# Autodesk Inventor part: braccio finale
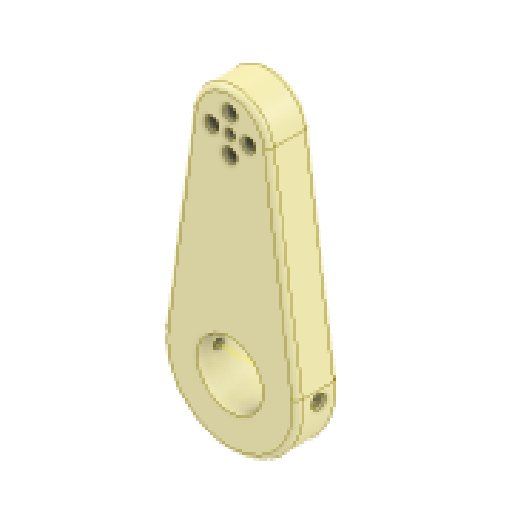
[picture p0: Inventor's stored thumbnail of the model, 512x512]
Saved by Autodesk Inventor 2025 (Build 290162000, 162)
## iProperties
Created: 2025-05
Part Number: braccio finale
Material: Nylon 6/6
Document SubType Name: Modeling
Designer: Ryzen5700u
Density: 1.13 g/cm^3
Appearance: Nylon 6
Author: Ryzen5700u
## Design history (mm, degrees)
sketch "Schizzo1"
  geometry: L1 (-25.751, 3.591)-(-14.807, 82.072); L2 (25.755, 3.559)-(14.908, 82.053); C1 r 12.55 at (0, 0); C2 r 2 at (0.049, 80); A1 r 26 centre (0, 0) between (25.755, 3.559) and (-25.751, 3.591); A2 r 15 centre (0.049, 80) between (-14.807, 82.072) and (14.908, 82.053); 2 further points
  constraints: 4 centre point, 4 coincident, 4 end point, 4 point on circle, 4 tangent
  dimensions: "d0" = 52 diameter of A1; "d2" = 25.1 diameter of C1; "d28" = 4 diameter of C2; "d29" = 30 diameter of A2; "d30" = 80 distance of point (0.049, 80) point (0, 0)
extrude "Estrusione1" new body sketch "Schizzo1" distance "d3" = 16; taper "d4" = 0 deg
fillet "Raccordo1" dims "d5" = 1
sketch "Schizzo5"
  geometry: C1 r 2 at (-0.049, 80) reference; 2 further points
  constraints: 1 coincident
hole "Foro4" sketch "Schizzo5" at (-0.049, 80) diameter "d31" = 3.4; stored, may be unused: countersink angle "d35" = 90 deg, drill point angle "d37" = 118 deg; dims "d32" = 6, "d33" = 7, "d34" = 5, "d36" = 8
sketch "Schizzo6"
  geometry: L1 (-12.55, 16)-(12.55, 16) reference; C1 r 1.6 at (0, 8); 2 further points
  constraints: 1 centre point, 1 coincident
  dimensions: "d38" = 8 distance from line of L1 point (0, 8); "d39" = 3.2 diameter of C1
extrude "Estrusione2" cut sketch "Schizzo6" extent not by distance; stored distance "d40" = 0; taper "d41" = 0 deg
node "Asse di lavoro1"
node "Piano di lavoro1"
sketch "Schizzo7"
  geometry: 4 further points
  constraints: 1 vertical alignment
hole "Foro5" sketch "Schizzo7" at (0, 8) diameter "d43" = 3.4; stored, may be unused: countersink angle "d47" = 90 deg, drill point angle "d49" = 118 deg; dims "d44" = 6, "d45" = 6, "d46" = 2, "d48" = 8
mirror "Speculare1"
fillet "Raccordo2" dims "d50" = 1
sketch "Schizzo9"
  geometry: L1 (13.917, 81.916)-(24.765, 3.422) reference; L2 (-24.76, 3.453)-(-13.817, 81.934) reference; C1 r 2 at (0.049, 80) reference; C2 r 12.55 at (0, 0) reference; C3 r 1.6 at (0.049, 73) reference; C4 r 1.6 at (0.049, 87) reference; C5 r 1.6 at (7.049, 80) reference; C6 r 1.6 at (-6.951, 80) reference; A1 r 25 centre (0, 0) between (-24.76, 3.453) and (24.765, 3.422) reference; A2 r 14 centre (0.049, 80) between (13.917, 81.916) and (-13.817, 81.934) reference; 1 further point
hole "Foro6" sketch "Schizzo9" at (-6.951, 80), (0.049, 73), (7.049, 80), (0.049, 87) diameter "d51" = 3.2; stored, may be unused: countersink angle "d55" = 90 deg, drill point angle "d57" = 118 deg; dims "d52" = 6, "d53" = 5.5, "d54" = 4, "d56" = 8
sketch "Schizzo11"
  geometry: C1 r 13.5 at (0, 0); C2 r 12.55 at (0, 0) reference; A1 r 26 centre (0, 0) between (-25.755, 3.559) and (25.751, 3.591) reference; 1 further point
  constraints: 1 centre point, 1 coincident
  dimensions: "d58" = 27 diameter of C1
extrude "Estrusione3" join sketch "Schizzo11" distance "d59" = 4; taper "d60" = 0 deg
node "Piano di lavoro2"
sketch "Schizzo12"
  geometry: C1 r 1.7 at (0, 8) reference; 2 further points
  constraints: 1 coincident
hole "Foro7" sketch "Schizzo12" at (0, 8) diameter "d62" = 3.4; stored, may be unused: countersink angle "d66" = 90 deg, drill point angle "d68" = 118 deg; dims "d63" = 6, "d64" = 5.5, "d65" = 4, "d67" = 8
node "Piano di lavoro3"
sketch "Schizzo13"
  geometry: L1 (-3.233, 8)-(-1.617, 10.8); L2 (-1.617, 10.8)-(1.617, 10.8); L3 (1.617, 10.8)-(3.233, 8); L4 (3.233, 8)-(1.617, 5.2); L5 (1.617, 5.2)-(-1.617, 5.2); L6 (-1.617, 5.2)-(-3.233, 8); C1 r 1.7 at (0, 8) reference; 3 further points
  constraints: 12 end point, 2 coincident, 13 other
  dimensions: "d70" = 5.6 distance between parallel lines of L5 L2
extrude "Estrusione4" cut sketch "Schizzo13" distance "d71" = 5; taper "d72" = 0 deg
fillet "Raccordo3" dims "d73" = 2
node "Solido1"
node "Linea chiusa proiettata1"
node "Riferimento9"
node "Riferimento10"
node "Riferimento11"
node "Riferimento12"
other parameters: "d42" = 21, "d61" = 28.5, "d69" = -28.5
